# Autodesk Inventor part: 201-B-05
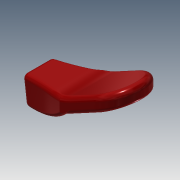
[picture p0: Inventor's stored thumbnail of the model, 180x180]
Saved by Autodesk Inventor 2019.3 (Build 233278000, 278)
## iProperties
Created: 2012-01
Part Number: 201-B-05
Material: Ogólny
Document SubType Name: Modeling
Designer: CADENGINEERING4
Density: 1 g/cm^3
Appearance: Czerwona
Author: CADENGINEERING4
Revision Number: ÈÎºÎ
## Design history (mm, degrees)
feature "Ô²½Ç2"
node "Bryła1"
